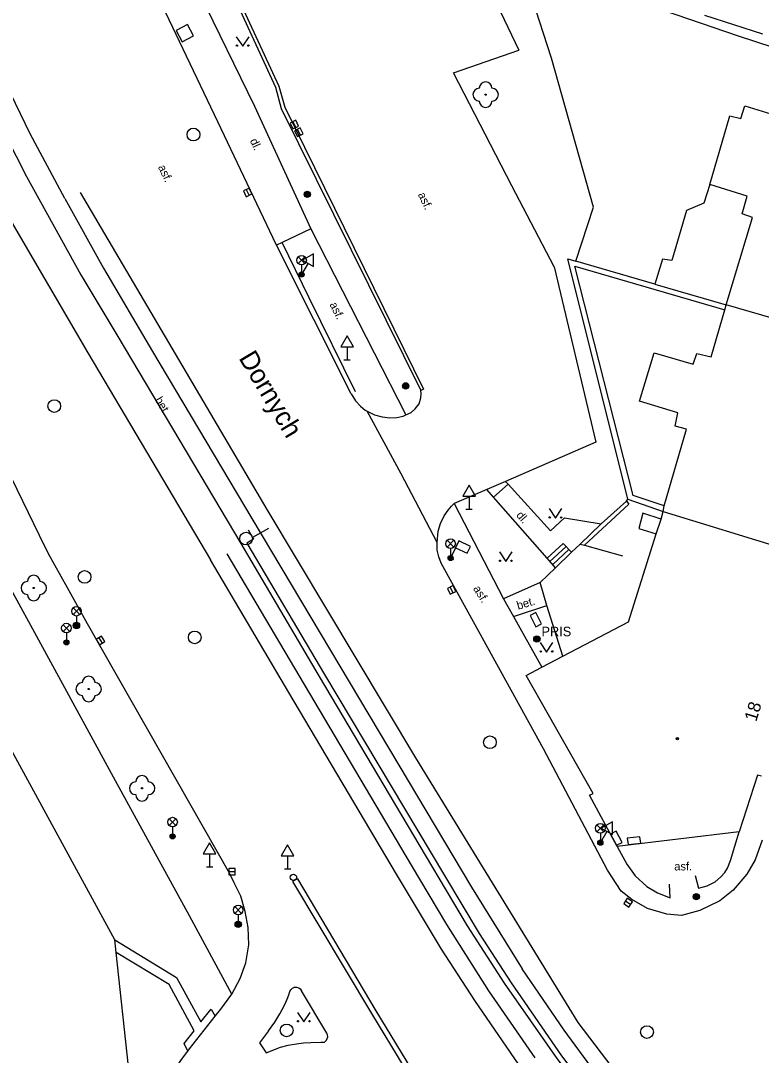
# Model space of a CAD drawing. Extents: x -598341 to -594502, y -1162301 to -1161406.
# Drawn here: x -597724.2 to -597666.1, y -1161529.1 to -1161447.8 of the extents above; entities that cross this region are included whole.
import ezdxf

# ---------------------------------------------------------------- set-up
doc = ezdxf.new("R2010")
doc.units = 0
for name, color, linetype in [('Vrstva 10', 7, 'Continuous'), ('Vrstva 11', 7, 'Continuous'), ('Vrstva 13', 7, 'Continuous'), ('Vrstva 22', 7, 'Continuous'), ('Vrstva 24', 7, 'Continuous'), ('Vrstva 25', 7, 'Continuous'), ('Vrstva 26', 7, 'Continuous'), ('Vrstva 27', 7, 'Continuous'), ('Vrstva 28', 7, 'Continuous'), ('Vrstva 33', 7, 'Continuous'), ('Vrstva 34', 7, 'Continuous'), ('Vrstva 36', 7, 'Continuous'), ('Vrstva 39', 7, 'Continuous'), ('Vrstva 40', 7, 'Continuous'), ('Vrstva 41', 7, 'Continuous'), ('Vrstva 46', 7, 'Continuous'), ('Vrstva 49', 7, 'Continuous'), ('Vrstva 5', 7, 'Continuous'), ('Vrstva 7', 7, 'Continuous'), ('Vrstva 9', 7, 'Continuous')]:
    doc.layers.add(name, color=color, linetype=linetype)

msp = doc.modelspace()

# ---------------------------------------------------------------- linework, layer by layer
at = {"layer": 'Vrstva 10'}
for p, q in [((-597682.31, -1161467.16), (-597685.63, -1161460.8)), ((-597682.31, -1161467.16), (-597679.04, -1161480.93)), ((-597679.04, -1161480.93), (-597686.11, -1161484)), ((-597686.11, -1161484), (-597687.59, -1161484.64)), ((-597687.59, -1161484.64), (-597690.14, -1161485.75))]:
    msp.add_line(p, q, dxfattribs=at)
for points in [[(-597699.7, -1161419.56), (-597685.07, -1161450.16)], [(-597704.08, -1161465.47), (-597708.7, -1161455.79), (-597713.31, -1161446.04), (-597717.79, -1161436.33), (-597720.99, -1161428.95)], [(-597710.03, -1161440.32), (-597704.17, -1161453.05), (-597703.72, -1161454.73), (-597692.76, -1161476.87)], [(-597685.63, -1161460.8), (-597690.2, -1161451.93), (-597685.07, -1161450.16)], [(-597707.77, -1161514.75), (-597713.03, -1161505.53), (-597718.92, -1161495.18), (-597720.49, -1161492.35), (-597721.97, -1161489.69), (-597722.69, -1161488.25), (-597727.51, -1161478.33), (-597731.33, -1161470.42), (-597732.42, -1161468.22), (-597733.33, -1161466.53), (-597737.86, -1161459.16), (-597741.59, -1161453.14)], [(-597698.24, -1161477.14), (-597704.08, -1161465.47)], [(-597698.24, -1161477.14), (-597697.9, -1161477.67), (-597697.5, -1161478.1), (-597697.12, -1161478.41), (-597696.98, -1161478.48)], [(-597693.94, -1161478.79), (-597693.53, -1161478.6), (-597693.2, -1161478.32), (-597692.9, -1161477.91), (-597692.77, -1161477.44), (-597692.74, -1161477.1), (-597692.76, -1161476.87)], [(-597696.98, -1161478.48), (-597696.4, -1161478.77), (-597695.8, -1161478.95), (-597695.2, -1161479.01), (-597694.64, -1161478.98), (-597694.16, -1161478.88), (-597693.94, -1161478.79)], [(-597691.49, -1161488.79), (-597691.41, -1161487.92), (-597691.23, -1161487.32), (-597690.92, -1161486.71), (-597690.63, -1161486.27), (-597690.35, -1161485.95), (-597690.14, -1161485.75)], [(-597691.18, -1161490.41), (-597691.35, -1161489.92), (-597691.47, -1161489.39), (-597691.49, -1161488.79)], [(-597678.12, -1161514.53), (-597683.15, -1161505), (-597691.18, -1161490.41)], [(-597665.98, -1161512.17), (-597666.53, -1161513.7), (-597667.19, -1161514.84), (-597668.25, -1161516.09), (-597669.3, -1161516.93), (-597670.87, -1161517.68), (-597672.32, -1161518.07), (-597673.47, -1161517.96), (-597674.97, -1161517.52), (-597676.21, -1161516.81), (-597677.04, -1161516.16), (-597678.12, -1161514.53)], [(-597707.58, -1161524.25), (-597706.93, -1161523.03), (-597706.5, -1161521.79), (-597706.27, -1161520.38), (-597706.32, -1161519.02), (-597706.55, -1161517.77), (-597706.88, -1161516.56), (-597707.42, -1161515.52), (-597707.77, -1161514.75)], [(-597704.71, -1161527.13), (-597704.22, -1161526.46), (-597703.83, -1161525.79), (-597703.46, -1161525.11), (-597703.26, -1161524.64), (-597703.12, -1161524.31), (-597703.05, -1161524.05), (-597702.97, -1161523.9), (-597702.84, -1161523.78), (-597702.68, -1161523.71), (-597702.52, -1161523.7), (-597702.34, -1161523.75), (-597702.22, -1161523.84), (-597702.12, -1161523.98)], [(-597708.46, -1161525.42), (-597707.58, -1161524.25)], [(-597700.15, -1161527.3), (-597702.12, -1161523.98)], [(-597708.89, -1161525.97), (-597708.46, -1161525.42)], [(-597710.91, -1161528.54), (-597708.89, -1161525.97)], [(-597704.71, -1161527.13), (-597705.43, -1161528.06), (-597704.9, -1161528.86), (-597703.78, -1161528.41)], [(-597700.33, -1161528.01), (-597700.23, -1161527.93), (-597700.17, -1161527.86), (-597700.1, -1161527.73), (-597700.07, -1161527.59), (-597700.08, -1161527.45), (-597700.11, -1161527.38), (-597700.15, -1161527.3)], [(-597711.05, -1161528.72), (-597710.91, -1161528.54)], [(-597703.78, -1161528.41), (-597703.18, -1161528.26), (-597702.53, -1161528.15), (-597701.98, -1161528.08), (-597701.38, -1161528.04), (-597700.62, -1161528.03)], [(-597700.62, -1161528.03), (-597700.33, -1161528.01)], [(-597714.41, -1161538.71), (-597714.39, -1161537.44), (-597714.27, -1161535.89), (-597713.99, -1161534.34), (-597713.55, -1161533.01), (-597712.96, -1161531.67), (-597712.32, -1161530.54), (-597711.55, -1161529.39), (-597711.05, -1161528.72)]]:
    msp.add_lwpolyline(points, dxfattribs=at)
at = {"layer": 'Vrstva 11'}
for p, q in [((-597680.82, -1161444.57), (-597667.88, -1161449.04)), ((-597667.88, -1161449.04), (-597665.15, -1161449.91)), ((-597704.83, -1161486.22), (-597719.46, -1161461.33)), ((-597701.38, -1161464.17), (-597703.63, -1161465.25)), ((-597703.63, -1161465.25), (-597704.08, -1161465.47)), ((-597681.24, -1161466.53), (-597680.61, -1161466.72)), ((-597676.52, -1161485.4), (-597681.24, -1161466.53)), ((-597674.4, -1161468.52), (-597680.61, -1161466.72)), ((-597673.81, -1161466.55), (-597674.4, -1161468.52)), ((-597716.53, -1161472.64), (-597706.88, -1161488.88)), ((-597692.55, -1161476.76), (-597692.76, -1161476.87)), ((-597687.07, -1161485.23), (-597687.59, -1161484.64)), ((-597687.07, -1161485.23), (-597685.91, -1161484.22)), ((-597682.85, -1161490.04), (-597687.07, -1161485.23)), ((-597706.32, -1161487.8), (-597705.97, -1161488.4)), ((-597704.72, -1161487.69), (-597705.97, -1161488.4)), ((-597706.88, -1161488.88), (-597700.73, -1161499.32)), ((-597705.88, -1161488.55), (-597706.42, -1161488.86)), ((-597706.42, -1161488.86), (-597700.32, -1161499.15)), ((-597705.97, -1161488.4), (-597705.88, -1161488.55)), ((-597682.63, -1161490.29), (-597681.37, -1161489.11)), ((-597682.42, -1161490.53), (-597681.15, -1161489.34)), ((-597680.25, -1161488.93), (-597679.92, -1161489.02)), ((-597679.92, -1161489.02), (-597676.95, -1161489.85)), ((-597682.2, -1161490.78), (-597682.85, -1161490.04)), ((-597683.41, -1161491.94), (-597686.28, -1161493.23)), ((-597685.48, -1161494.6), (-597682.87, -1161493.74)), ((-597700.73, -1161499.32), (-597692.43, -1161513.34)), ((-597700.32, -1161499.15), (-597690.9, -1161514.95))]:
    msp.add_line(p, q, dxfattribs=at)
for points in [[(-597718.33, -1161427.77), (-597715, -1161435.22), (-597710.17, -1161445.59), (-597705.81, -1161454.55), (-597701.38, -1161464.17)], [(-597709.81, -1161440.19), (-597703.91, -1161452.98), (-597703.44, -1161454.64), (-597692.55, -1161476.76)], [(-597707.58, -1161524.25), (-597710.92, -1161518.11), (-597716.71, -1161507.5), (-597721.48, -1161498.77), (-597726.18, -1161490.18), (-597730.65, -1161481.99), (-597735.17, -1161473.66), (-597737.96, -1161468.56), (-597741.75, -1161461.65), (-597745.31, -1161455.1), (-597747.59, -1161450.97), (-597749.99, -1161446.56)], [(-597670.52, -1161447.4), (-597665.97, -1161448.88)], [(-597729.37, -1161448.53), (-597726.18, -1161455.24), (-597723.7, -1161460.08)], [(-597723.7, -1161460.08), (-597719.45, -1161467.8), (-597716.53, -1161472.64)], [(-597670.1, -1161460.69), (-597670.55, -1161462.17), (-597671.93, -1161462.75), (-597673.07, -1161466.67), (-597673.81, -1161466.55)], [(-597724.9, -1161463.6), (-597718.9, -1161473.92), (-597709.26, -1161490.17)], [(-597701.38, -1161464.17), (-597693.94, -1161478.79)], [(-597691.49, -1161488.79), (-597694.3, -1161483.42), (-597696.98, -1161478.48)], [(-597686.11, -1161484), (-597685.91, -1161484.22)], [(-597685.91, -1161484.22), (-597682.6, -1161487.89), (-597681.5, -1161486.86), (-597678.61, -1161487.34)], [(-597676.64, -1161485.56), (-597676.44, -1161485.78), (-597679.92, -1161489.02)], [(-597678.61, -1161487.34), (-597676.64, -1161485.56)], [(-597676.64, -1161485.56), (-597676.52, -1161485.4)], [(-597680.41, -1161526.47), (-597693.16, -1161505.7), (-597704.83, -1161486.22)], [(-597690.14, -1161485.75), (-597686.28, -1161493.23)], [(-597673.92, -1161486.98), (-597675.34, -1161486.49), (-597675.66, -1161487.7), (-597674.31, -1161488.11)], [(-597680.25, -1161488.93), (-597678.61, -1161487.34)], [(-597682.85, -1161490.04), (-597681.6, -1161488.87), (-597680.93, -1161489.57)], [(-597682.2, -1161490.78), (-597680.93, -1161489.57)], [(-597680.93, -1161489.57), (-597680.25, -1161488.93)], [(-597685.09, -1161529.74), (-597688.52, -1161524.75), (-597691.14, -1161520.72), (-597694.67, -1161514.82), (-597703.12, -1161500.58), (-597709.26, -1161490.17)], [(-597683.41, -1161491.94), (-597682.2, -1161490.78)], [(-597682.87, -1161493.74), (-597683.41, -1161491.94)], [(-597686.28, -1161493.23), (-597685.48, -1161494.6)], [(-597681.61, -1161497.72), (-597682.87, -1161493.74)], [(-597685.48, -1161494.6), (-597683.28, -1161498.59)], [(-597692.43, -1161513.34), (-597689.12, -1161518.9), (-597686.23, -1161523.39)], [(-597702.44, -1161515.19), (-597702.82, -1161515.41), (-597696.64, -1161525.77), (-597691.56, -1161534.13), (-597682.04, -1161549.82), (-597681.57, -1161551.71), (-597681.13, -1161551.61)], [(-597702.44, -1161515.19), (-597696.29, -1161525.55), (-597691.13, -1161534.03), (-597681.68, -1161549.59), (-597681.13, -1161551.61)], [(-597690.9, -1161514.95), (-597688.19, -1161519.5), (-597685.67, -1161523.37)], [(-597716.77, -1161519.98), (-597711.92, -1161522.94), (-597710.01, -1161526.43), (-597709.2, -1161525.43), (-597708.89, -1161525.97)], [(-597711.05, -1161528.72), (-597711.34, -1161528.13), (-597710.54, -1161527.12), (-597712.51, -1161523.5), (-597716.66, -1161520.97)], [(-597686.23, -1161523.39), (-597682.1, -1161529.31), (-597678.86, -1161533.58)], [(-597685.67, -1161523.37), (-597681.72, -1161529.09), (-597678.5, -1161533.34)], [(-597652.22, -1161555.75), (-597656.49, -1161552.39), (-597660.57, -1161548.82), (-597664.79, -1161544.83), (-597667.4, -1161542.15), (-597670.61, -1161538.74), (-597673.7, -1161535.17), (-597676.33, -1161531.84), (-597680.41, -1161526.47)]]:
    msp.add_lwpolyline(points, dxfattribs=at)
at = {"layer": 'Vrstva 13'}
for points in [[(-597720.7, -1161461.81), (-597723.41, -1161456.73), (-597726.88, -1161449.59), (-597729.13, -1161444.41), (-597731.23, -1161438.9), (-597732.46, -1161435.27), (-597734.12, -1161430), (-597735.38, -1161425.18), (-597736.79, -1161418.8), (-597738, -1161411.98)], [(-597720.7, -1161461.81), (-597717.65, -1161467.26), (-597713.82, -1161473.8), (-597706.02, -1161486.93), (-597694.5, -1161506.28), (-597688.8, -1161515.85), (-597684.82, -1161522.26)], [(-597707.99, -1161489.7), (-597701.92, -1161499.94), (-597693.52, -1161514.12), (-597690.76, -1161518.79), (-597687.46, -1161523.99), (-597683.83, -1161529.24)], [(-597653.41, -1161556.45), (-597658.42, -1161552.42), (-597663.98, -1161547.39), (-597668.89, -1161542.4), (-597672.85, -1161538.1), (-597676.25, -1161534), (-597679.14, -1161530.31), (-597681.52, -1161527.07), (-597684.82, -1161522.26)]]:
    msp.add_lwpolyline(points, dxfattribs=at)
at = {"layer": 'Vrstva 22'}
for centre in [(-597687.68, -1161453.65), (-597723.13, -1161492.37), (-597718.82, -1161500.3), (-597714.63, -1161508.09)]:
    msp.add_circle(centre, 0.05, dxfattribs=at)
for centre, start, end in [((-597688.18, -1161453.65), 90, 270), ((-597687.68, -1161453.15), 0, 180), ((-597687.18, -1161453.65), 270, 90), ((-597687.68, -1161454.15), 180, 0), ((-597723.63, -1161492.37), 90, 270), ((-597723.13, -1161491.87), 0, 180), ((-597722.63, -1161492.37), 270, 90), ((-597723.13, -1161492.87), 180, 0), ((-597718.82, -1161499.8), 0, 180), ((-597719.32, -1161500.3), 90, 270), ((-597718.32, -1161500.3), 270, 90), ((-597718.82, -1161500.8), 180, 0), ((-597715.13, -1161508.09), 90, 270), ((-597714.63, -1161507.59), 0, 180), ((-597714.13, -1161508.09), 270, 90), ((-597714.63, -1161508.59), 180, 0)]:
    msp.add_arc(centre, 0.5, start, end, dxfattribs=at)
at = {"layer": 'Vrstva 24'}
for points in [[(-597684.192, -1161494.522), (-597683.731, -1161495.409), (-597683.287, -1161495.178), (-597683.749, -1161494.291)], [(-597677.871, -1161511.68), (-597677.414, -1161512.568), (-597676.969, -1161512.34), (-597677.427, -1161511.451)], [(-597676.51, -1161512.513), (-597675.516, -1161512.404), (-597675.57, -1161511.907), (-597676.564, -1161512.016)]]:
    msp.add_lwpolyline(points, close=True, dxfattribs=at)
at = {"layer": 'Vrstva 25'}
for centre, radius in [((-597701.67, -1161461.47), 0.25), ((-597701.67, -1161461.47), 0.2), ((-597701.67, -1161461.47), 0.15), ((-597701.67, -1161461.47), 0.1), ((-597701.67, -1161461.47), 0.05), ((-597693.95, -1161476.51), 0.25), ((-597693.95, -1161476.51), 0.2), ((-597693.95, -1161476.51), 0.15), ((-597693.95, -1161476.51), 0.1), ((-597693.95, -1161476.51), 0.05), ((-597719.78, -1161495.32), 0.25), ((-597719.78, -1161495.32), 0.2), ((-597719.78, -1161495.32), 0.15), ((-597719.78, -1161495.32), 0.1), ((-597719.78, -1161495.32), 0.05), ((-597683.66, -1161496.37), 0.25), ((-597683.66, -1161496.37), 0.2), ((-597683.66, -1161496.37), 0.15), ((-597683.66, -1161496.37), 0.1), ((-597683.66, -1161496.37), 0.05), ((-597671.15, -1161516.6), 0.25), ((-597671.15, -1161516.6), 0.2), ((-597671.15, -1161516.6), 0.15), ((-597671.15, -1161516.6), 0.1), ((-597671.15, -1161516.6), 0.05), ((-597707.09, -1161518.77), 0.25), ((-597707.09, -1161518.77), 0.2), ((-597707.09, -1161518.77), 0.15), ((-597707.09, -1161518.77), 0.1), ((-597707.09, -1161518.77), 0.05)]:
    msp.add_circle(centre, radius, dxfattribs=at)
at = {"layer": 'Vrstva 26'}
msp.add_lwpolyline([(-597711.492, -1161449.495), (-597710.605, -1161449.032), (-597711.068, -1161448.145), (-597711.955, -1161448.608)], close=True, dxfattribs=at)
at = {"layer": 'Vrstva 27'}
for p, q in [((-597702.801, -1161455.776), (-597702.58, -1161456.224)), ((-597702.441, -1161456.376), (-597702.22, -1161456.824)), ((-597706.457, -1161461.104), (-597706.242, -1161461.555)), ((-597690.457, -1161492.294), (-597690.243, -1161492.746)), ((-597718.032, -1161496.278), (-597717.768, -1161496.702)), ((-597707.82, -1161514.63), (-597707.32, -1161514.63)), ((-597676.706, -1161516.928), (-597676.295, -1161517.213))]:
    msp.add_line(p, q, dxfattribs=at)
for points in [[(-597703.025, -1161455.886), (-597702.804, -1161456.335), (-597702.355, -1161456.113), (-597702.577, -1161455.665)], [(-597702.665, -1161456.486), (-597702.444, -1161456.935), (-597701.995, -1161456.713), (-597702.217, -1161456.265)], [(-597706.683, -1161461.212), (-597706.467, -1161461.663), (-597706.016, -1161461.447), (-597706.232, -1161460.996)], [(-597690.683, -1161492.401), (-597690.469, -1161492.853), (-597690.017, -1161492.639), (-597690.231, -1161492.187)], [(-597718.244, -1161496.408), (-597717.982, -1161496.834), (-597717.556, -1161496.572), (-597717.818, -1161496.146)], [(-597707.82, -1161514.88), (-597707.32, -1161514.88), (-597707.32, -1161514.38), (-597707.82, -1161514.38)], [(-597676.848, -1161517.133), (-597676.438, -1161517.418), (-597676.152, -1161517.008), (-597676.563, -1161516.722)]]:
    msp.add_lwpolyline(points, close=True, dxfattribs=at)
for centre in [(-597710.6, -1161456.78), (-597721.52, -1161478.09), (-597706.47, -1161488.49), (-597719.14, -1161491.5), (-597710.5, -1161496.25), (-597687.34, -1161504.48), (-597703.29, -1161527.1), (-597675.02, -1161527.23)]:
    msp.add_circle(centre, 0.5, dxfattribs=at)
at = {"layer": 'Vrstva 28'}
msp.add_circle((-597702.76, -1161515.08), 0.25, dxfattribs=at)
at = {"layer": 'Vrstva 33'}
for p, q in [((-597702.385, -1161466.91), (-597701.855, -1161466.38)), ((-597702.385, -1161466.38), (-597701.855, -1161466.91)), ((-597702.12, -1161467.02), (-597702.12, -1161467.77)), ((-597690.695, -1161489.16), (-597690.165, -1161488.63)), ((-597690.695, -1161488.63), (-597690.165, -1161489.16)), ((-597690.43, -1161489.27), (-597690.43, -1161490.02)), ((-597720.045, -1161494.46), (-597719.515, -1161493.93)), ((-597720.045, -1161493.93), (-597719.515, -1161494.46)), ((-597719.78, -1161494.57), (-597719.78, -1161495.32)), ((-597720.835, -1161495.78), (-597720.305, -1161495.25)), ((-597720.835, -1161495.25), (-597720.305, -1161495.78)), ((-597720.57, -1161495.89), (-597720.57, -1161496.64)), ((-597712.505, -1161511.01), (-597711.975, -1161510.48)), ((-597712.505, -1161510.48), (-597711.975, -1161511.01)), ((-597712.24, -1161511.12), (-597712.24, -1161511.87)), ((-597678.945, -1161511.5), (-597678.415, -1161510.97)), ((-597678.945, -1161510.97), (-597678.415, -1161511.5)), ((-597678.68, -1161511.61), (-597678.68, -1161512.36)), ((-597707.355, -1161517.91), (-597706.825, -1161517.38)), ((-597707.355, -1161517.38), (-597706.825, -1161517.91)), ((-597707.09, -1161518.02), (-597707.09, -1161518.77))]:
    msp.add_line(p, q, dxfattribs=at)
for centre, radius in [((-597702.12, -1161466.645), 0.375), ((-597702.12, -1161467.77), 0.2), ((-597702.12, -1161467.77), 0.145), ((-597702.12, -1161467.77), 0.0876), ((-597690.43, -1161488.895), 0.375), ((-597690.43, -1161490.02), 0.2), ((-597690.43, -1161490.02), 0.145), ((-597690.43, -1161490.02), 0.0876), ((-597719.78, -1161494.195), 0.375), ((-597720.57, -1161495.515), 0.375), ((-597719.78, -1161495.32), 0.2), ((-597719.78, -1161495.32), 0.145), ((-597719.78, -1161495.32), 0.0876), ((-597720.57, -1161496.64), 0.2), ((-597720.57, -1161496.64), 0.145), ((-597720.57, -1161496.64), 0.0876), ((-597712.24, -1161510.745), 0.375), ((-597678.68, -1161511.235), 0.375), ((-597712.24, -1161511.87), 0.2), ((-597712.24, -1161511.87), 0.145), ((-597712.24, -1161511.87), 0.0876), ((-597678.68, -1161512.36), 0.2), ((-597678.68, -1161512.36), 0.145), ((-597678.68, -1161512.36), 0.0876), ((-597707.09, -1161517.645), 0.375), ((-597707.09, -1161518.77), 0.2), ((-597707.09, -1161518.77), 0.145), ((-597707.09, -1161518.77), 0.0876)]:
    msp.add_circle(centre, radius, dxfattribs=at)
at = {"layer": 'Vrstva 34'}
for p, q in [((-597701.611, -1161466.888), (-597702.12, -1161467.77)), ((-597702.337, -1161467.645), (-597701.903, -1161467.895)), ((-597698.55, -1161473.452), (-597698.55, -1161474.47)), ((-597698.8, -1161474.47), (-597698.3, -1161474.47)), ((-597688.98, -1161485.172), (-597688.98, -1161486.19)), ((-597689.23, -1161486.19), (-597688.73, -1161486.19)), ((-597690.035, -1161489.211), (-597690.43, -1161490.02)), ((-597690.655, -1161489.91), (-597690.205, -1161490.13)), ((-597678.171, -1161511.478), (-597678.68, -1161512.36)), ((-597678.897, -1161512.235), (-597678.463, -1161512.485)), ((-597709.34, -1161513.232), (-597709.34, -1161514.25)), ((-597703.22, -1161513.392), (-597703.22, -1161514.41)), ((-597709.59, -1161514.25), (-597709.09, -1161514.25)), ((-597703.47, -1161514.41), (-597702.97, -1161514.41))]:
    msp.add_line(p, q, dxfattribs=at)
for points in [[(-597702.044, -1161466.638), (-597701.178, -1161467.138), (-597701.178, -1161466.138)], [(-597699.05, -1161473.452), (-597698.05, -1161473.452), (-597698.55, -1161472.586)], [(-597689.48, -1161485.172), (-597688.48, -1161485.172), (-597688.98, -1161484.306)], [(-597690.035, -1161489.211), (-597689.136, -1161489.65), (-597688.873, -1161489.111), (-597689.772, -1161488.672)], [(-597678.604, -1161511.228), (-597677.738, -1161511.728), (-597677.738, -1161510.728)], [(-597709.84, -1161513.232), (-597708.84, -1161513.232), (-597709.34, -1161512.366)], [(-597703.72, -1161513.392), (-597702.72, -1161513.392), (-597703.22, -1161512.526)]]:
    msp.add_lwpolyline(points, close=True, dxfattribs=at)
at = {"layer": 'Vrstva 36'}
for points in [[(-597707.24, -1161449.1), (-597706.74, -1161449.85), (-597706.24, -1161449.1)], [(-597682.7, -1161486.13), (-597682.2, -1161486.88), (-597681.7, -1161486.13)], [(-597686.6, -1161489.53), (-597686.1, -1161490.28), (-597685.6, -1161489.53)], [(-597683.4, -1161496.65), (-597682.9, -1161497.4), (-597682.4, -1161496.65)], [(-597702.45, -1161525.68), (-597701.95, -1161526.43), (-597701.45, -1161525.68)]]:
    msp.add_lwpolyline(points, dxfattribs=at)
for centre in [(-597707.19, -1161449.8), (-597706.291, -1161449.8), (-597682.65, -1161486.829), (-597681.751, -1161486.829), (-597686.551, -1161490.23), (-597685.651, -1161490.23), (-597683.351, -1161497.349), (-597682.451, -1161497.349), (-597702.4, -1161526.38), (-597701.5, -1161526.38)]:
    msp.add_circle(centre, 0.05, dxfattribs=at)
at = {"layer": 'Vrstva 39'}
for radius in [0.09, 0.0398]:
    msp.add_circle((-597672.63, -1161504.19), radius, dxfattribs=at)
at = {"layer": 'Vrstva 5'}
for p, q in [((-597667.66, -1161455.53), (-597667.34, -1161454.53)), ((-597667.34, -1161454.53), (-597664.29, -1161455.48)), ((-597670.1, -1161460.69), (-597668.53, -1161455.31)), ((-597668.53, -1161455.31), (-597667.66, -1161455.53)), ((-597667.15, -1161461.62), (-597670.1, -1161460.69)), ((-597667.56, -1161463), (-597667.15, -1161461.62)), ((-597668.8, -1161470.14), (-597666.73, -1161463.29)), ((-597666.73, -1161463.29), (-597667.56, -1161463)), ((-597668.92, -1161470.53), (-597668.8, -1161470.14)), ((-597656.08, -1161473.84), (-597668.8, -1161470.14)), ((-597669.98, -1161474.22), (-597668.92, -1161470.53)), ((-597675.62, -1161477.71), (-597674.47, -1161473.92)), ((-597674.47, -1161473.92), (-597671.41, -1161474.81)), ((-597671.41, -1161474.81), (-597671.11, -1161473.96)), ((-597671.11, -1161473.96), (-597669.98, -1161474.22)), ((-597672.6, -1161478.63), (-597675.62, -1161477.71)), ((-597672.81, -1161479.68), (-597672.6, -1161478.63)), ((-597673.66, -1161485.93), (-597671.93, -1161479.91)), ((-597671.93, -1161479.91), (-597672.81, -1161479.68)), ((-597673.92, -1161486.98), (-597673.74, -1161486.38)), ((-597673.74, -1161486.38), (-597673.66, -1161485.93)), ((-597673.74, -1161486.38), (-597660.96, -1161490.28)), ((-597674.31, -1161488.11), (-597673.92, -1161486.98)), ((-597676.48, -1161495.03), (-597674.31, -1161488.11)), ((-597681.61, -1161497.72), (-597676.48, -1161495.03)), ((-597716.77, -1161519.98), (-597729.45, -1161496.74)), ((-597683.28, -1161498.59), (-597681.61, -1161497.72)), ((-597684.51, -1161499.24), (-597683.28, -1161498.59)), ((-597679.25, -1161508.5), (-597684.51, -1161499.24)), ((-597666.34, -1161507.07), (-597667.79, -1161511.51)), ((-597666.04, -1161507.15), (-597666.34, -1161507.07)), ((-597679.52, -1161508.64), (-597679.25, -1161508.5)), ((-597677.35, -1161512.67), (-597679.52, -1161508.64)), ((-597667.79, -1161511.51), (-597677.35, -1161512.67)), ((-597716.66, -1161520.97), (-597716.77, -1161519.98)), ((-597715.69, -1161529.92), (-597716.66, -1161520.97))]:
    msp.add_line(p, q, dxfattribs=at)
at = {"layer": 'Vrstva 7'}
for p, q in [((-597682.5, -1161450.79), (-597684.93, -1161443.36)), ((-597674.4, -1161468.52), (-597668.8, -1161470.14)), ((-597676.52, -1161485.4), (-597673.74, -1161486.38))]:
    msp.add_line(p, q, dxfattribs=at)
for points in [[(-597680.61, -1161466.72), (-597679.21, -1161462.48), (-597682.5, -1161450.79)], [(-597673.66, -1161485.93), (-597676.1, -1161485.11), (-597680.68, -1161467.11), (-597668.92, -1161470.53)]]:
    msp.add_lwpolyline(points, dxfattribs=at)
at = {"layer": 'Vrstva 9'}
for points in [[(-597697.89, -1161476.97), (-597701.53, -1161469.59), (-597703.63, -1161465.25)], [(-597671.24, -1161514.93), (-597670.98, -1161515.92), (-597670.31, -1161515.76), (-597669.66, -1161515.43), (-597669.22, -1161515.05), (-597668.91, -1161514.7), (-597668.71, -1161514.35), (-597668.48, -1161513.75), (-597667.79, -1161511.51)], [(-597677.35, -1161512.67), (-597676.61, -1161514.04), (-597675.95, -1161514.97), (-597675.04, -1161515.79), (-597674.19, -1161516.31), (-597673.2, -1161516.69), (-597673.25, -1161515.61)]]:
    msp.add_lwpolyline(points, dxfattribs=at)

# ---------------------------------------------------------------- texts
at = {"layer": 'Vrstva 40'}
for s, rotation, p in [('dl.', 294.53497, (-597706.19, -1161457.26)), ('asf.', 295.42028, (-597713.4, -1161459.33)), ('asf.', 295.42028, (-597693.01, -1161461.49)), ('asf.', 296.02226, (-597699.94, -1161470.11)), ('bet.', 300.7074, (-597713.65, -1161477.6)), ('dl.', 310.23636, (-597685.32, -1161486.68)), ('asf.', 302.09409, (-597688.69, -1161492.42)), ('bet.', 16.64595, (-597685.13, -1161494.08))]:
    msp.add_text(s, height=0.65, rotation=rotation, dxfattribs=at).set_placement(p)
msp.add_text('asf.', height=0.65, dxfattribs=at).set_placement((-597672.88, -1161514.54))
at = {"layer": 'Vrstva 41'}
msp.add_text('PRIS', height=0.75, dxfattribs=at).set_placement((-597683.3, -1161496.16))
at = {"layer": 'Vrstva 46'}
msp.add_text('18', height=1, rotation=72.95, dxfattribs=at).set_placement((-597666.45, -1161502.91))
at = {"layer": 'Vrstva 49'}
msp.add_text('Dornych', height=1.5, rotation=300.89731, dxfattribs=at).set_placement((-597707.09, -1161474.32))

doc.saveas('drawing.dxf')
